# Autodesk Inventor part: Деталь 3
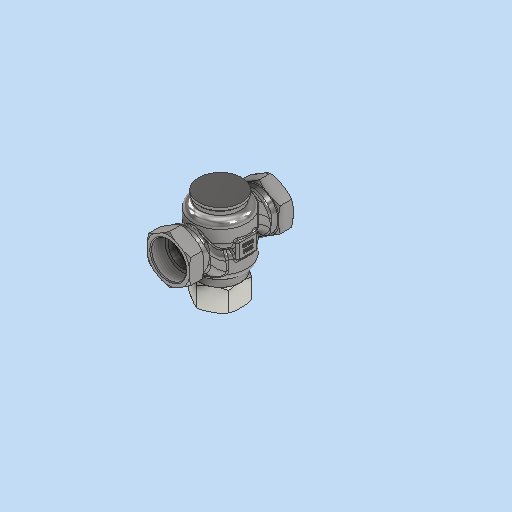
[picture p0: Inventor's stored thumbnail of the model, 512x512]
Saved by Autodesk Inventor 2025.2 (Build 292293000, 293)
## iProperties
Created: 2026-04
Part Number: Деталь 3
Material: Типовые
Document SubType Name: Modeling
Designer: igorr
Density: 1 g/cm^3
Appearance: По умолчанию
Author: igorr
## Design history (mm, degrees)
node "РабПлоскость1"
sketch "Эскиз3"
  geometry: L1 (-23.475, 13.553)-(0, 27.107); L2 (0, 27.107)-(23.475, 13.553); L3 (23.475, 13.553)-(23.475, -13.553); L4 (23.475, -13.553)-(0, -27.107); L5 (0, -27.107)-(-23.475, -13.553); L6 (-23.475, -13.553)-(-23.475, 13.553); C1 r 19.475 at (0, 0); 3 further points
  constraints: 12 end point, 2 coincident, 1 centre point, 1 horizontal alignment, 1 midpoint, 15 other
  dimensions: "d9" = 38.95 diameter of C1; "d10" = 4 dimension on C1
extrude "Выдавливание3" new body sketch "Эскиз3" distance "d11" = 16; taper "d12" = 0 deg
sketch "Эскиз4"
  geometry: C1 r 19.475 at (0, 0) reference; C2 r 22.475 at (0, 0); C3 r 16 at (0, 0); 1 further point
  constraints: 2 centre point, 1 coincident
  dimensions: "d13" = 3 radial gap between concentric circles of C1 C2; "d14" = 32 diameter of C3
extrude "Выдавливание4" join sketch "Эскиз4" distance "d15" = 8; taper "d16" = 0 deg
sketch "Эскиз5"
  geometry: L1 (-19.475, -58)-(19.475, -58) reference; L2 (0, -58)-(0, -66.797); L3 (13.553, -58)-(27.107, -58) reference; L4 (27.107, -58)-(24.107, -58); L5 (24.107, -58)-(29.957, -54.622); L6 (29.957, -54.622)-(29.957, -58); L7 (29.957, -58)-(24.107, -58); L8 (27.107, -58)-(27.107, -42) reference; L9 (27.107, -50)-(28.741, -50); L10 (24.107, -42)-(29.957, -45.378); L11 (29.957, -45.378)-(29.957, -42); L12 (29.957, -42)-(24.107, -42); 2 further points
  constraints: 18 end point, 3 symmetric about line, 2 midpoint, 2 point on line, 1 collinear, 1 horizontal, 1 perpendicular, 1 vertical
  dimensions: "d17" = 3 distance of L3.end L4.end; "d18" = 30 deg angle of L4 L5
revolve "Вращение1" sketch "Эскиз5" stored, may be unused: angle "d19" = 90 deg
node "РабПлоскость4"
sketch "Эскиз13"
  geometry: L1 (15, 30)-(-15, 30); L2 (-25, 20)-(-25, 10); L3 (-15, 0)-(15, 0); L4 (25, 10)-(25, 20); L5 (25, 30)-(-25, 0); L6 (-25, 30)-(25, 0); A1 r 10 centre (15, 20) between (25, 20) and (15, 30); A2 r 10 centre (-15, 20) between (-15, 30) and (-25, 20); A3 r 10 centre (-15, 10) between (-25, 10) and (-15, 0); A4 r 10 centre (15, 10) between (15, 0) and (25, 10); 2 further points
  constraints: 12 end point, 8 point on circle, 8 point on line, 8 tangent, 4 centre point, 3 equal radius, 3 midpoint, 2 parallel, 1 horizontal, 1 perpendicular
  dimensions: "d60" = 50 distance of L5.start L6.start; "d61" = 30 distance of L5.end L6.start; "d62" = 10 radius of A1
feature "Лофт3" sketch "Эскиз13" dims "d63" = 0, "d64" = 90 deg, "d65" = 10, "d66" = 90 deg
  node "Ребра5"
fillet "Сопряжение11" dims "d73" = 7
mirror "Зеркальное отражение6"
mirror "Зеркальное отражение7"
sketch "Эскиз15"
  geometry: C1 r 30 at (0, 0); 1 further point
  constraints: 1 centre point, 1 coincident
  dimensions: "d74" = 60 diameter of C1
extrude "Выдавливание9" join sketch "Эскиз15" distance "d75" = 30; taper "d76" = 0 deg
fillet "Сопряжение12" dims "d77" = 8
sketch "Эскиз16"
  geometry: C1 r 30 at (0, 0); 1 further point
  constraints: 1 centre point, 1 coincident
  dimensions: "d78" = 60 diameter of C1
extrude "Выдавливание10" join sketch "Эскиз16" distance "d79" = 30; taper "d80" = 0 deg
fillet "Сопряжение13" dims "d81" = 8
feature "Комбинировать1"
  node "Твердое тело3"
sketch "Эскиз17"
  geometry: L1 (-10, 11.5)-(10, 11.5); L2 (10, 11.5)-(10, -11.5); L3 (10, -11.5)-(-10, -11.5); L4 (-10, -11.5)-(-10, 11.5); L5 (-10, 11.5)-(10, -11.5); L6 (10, 11.5)-(-10, -11.5); 1 further point
  constraints: 12 end point, 2 midpoint, 2 parallel, 1 horizontal, 1 perpendicular
  dimensions: "d83" = 20 distance of L1.start L1.end; "d84" = 23 distance of L1.end L2.end
extrude "Выдавливание11" join sketch "Эскиз17" distance "d85" = 31; taper "d86" = 0 deg
sketch "Эскиз18"
  geometry: C1 r 23 at (0, 0); 1 further point
  constraints: 1 centre point, 1 coincident
  dimensions: "d88" = 46 diameter of C1
extrude "Выдавливание12" join sketch "Эскиз18" distance "d89" = 9; taper "d90" = 0 deg; dims "d119" = 6.5, "d120" = 0
sketch "Эскиз19"
  geometry: L1 (22.475, -12.976)-(0, -25.952); L2 (0, -25.952)-(-22.475, -12.976); L3 (-22.475, -12.976)-(-22.475, 12.976); L4 (-22.475, 12.976)-(0, 25.952); L5 (0, 25.952)-(22.475, 12.976); L6 (22.475, 12.976)-(22.475, -12.976); C1 r 19.475 at (0, 0); 3 further points
  constraints: 12 end point, 2 coincident, 1 centre point, 1 horizontal alignment, 1 midpoint, 15 other
  dimensions: "d91" = 38.95 diameter of C1; "d92" = 3 dimension on C1
extrude "Выдавливание13" join sketch "Эскиз19" distance "d94" = 25; taper "d95" = 0 deg
sketch "Эскиз20"
  geometry: C1 r 16 at (0, 0); 1 further point
  constraints: 1 centre point, 1 coincident
  dimensions: "d96" = 32 diameter of C1
extrude "Выдавливание14" cut sketch "Эскиз20" distance "d97" = 17; taper "d98" = 0 deg
sketch "Эскиз21"
  geometry: L1 (-64, -25.952)-(-64, -12.976) reference; L2 (-64, -25.952)-(-64, -22.952); L3 (-64, -22.952)-(-62.268, -25.952); L4 (-39, -25.952)-(-64, -25.952) reference; L5 (-62.268, -25.952)-(-64, -25.952); L6 (-64, 12.976)-(-64, -12.976) reference; L7 (-64, 0)-(-69.309, 0); L8 (-51.5, -25.952)-(-51.5, -19.962); L9 (-39, -25.952)-(-39, -22.952); L10 (-39, -22.952)-(-40.732, -25.952); L11 (-40.732, -25.952)-(-39, -25.952); 2 further points
  constraints: 16 end point, 2 midpoint, 2 point on line, 2 symmetric about line, 1 collinear, 1 horizontal, 1 vertical
  dimensions: "d99" = 3 distance of L1.start L2.end; "d100" = 30 deg angle of L2 L3
revolve "Вращение2" sketch "Эскиз21" stored, may be unused: angle "d101" = 360 deg
sketch "Эскиз22"
  geometry: C1 r 16 at (0, 0) reference; C2 r 22 at (0, 0); 1 further point
  constraints: 1 centre point, 1 coincident
  dimensions: "d103" = 44 diameter of C2
extrude "Выдавливание15" join sketch "Эскиз22" distance "d104" = 9; taper "d105" = 0 deg
sketch "Эскиз23"
  geometry: L1 (-6.1, 4.97)-(6.161, 4.97); L2 (6.161, 4.97)-(6.161, 1.858); L3 (6.161, 1.858)-(-6.1, 1.858); L4 (-6.1, 1.858)-(-6.1, 4.97); 1 further point
  constraints: 2 other
feature "Рельеф1" sketch "Эскиз23" dims "d17" = 3, "d18" = 30 deg, "d106" = 0.5, "d107" = 0
chamfer "Фаска1" distance "d108" = 1; stored, may be unused: second distance "d109" = 2, angle "d110" = 45 deg
sketch "Эскиз24"
  geometry: C1 r 24 at (0, 0); 1 further point
  constraints: 1 centre point, 1 coincident
  dimensions: "d111" = 48 diameter of C1
extrude "Выдавливание16" join sketch "Эскиз24" distance "d112" = 4; taper "d113" = 0 deg
feature "Резьба1" dims "d115" = 114, "d116" = 0
feature "Резьба2" dims "d117" = 24, "d118" = 0
fillet "Сопряжение18" dims "d121" = 2
fillet "Сопряжение20" dims "d123" = 2
fillet "Сопряжение22" dims "d125" = 1
fillet "Сопряжение23" dims "d126" = 1
fillet "Сопряжение24" dims "d127" = 5
node "Твердое тело2"
feature "Шаблон Твердое тело2:1"
other parameters: "d8" = -58, "d54" = 25
